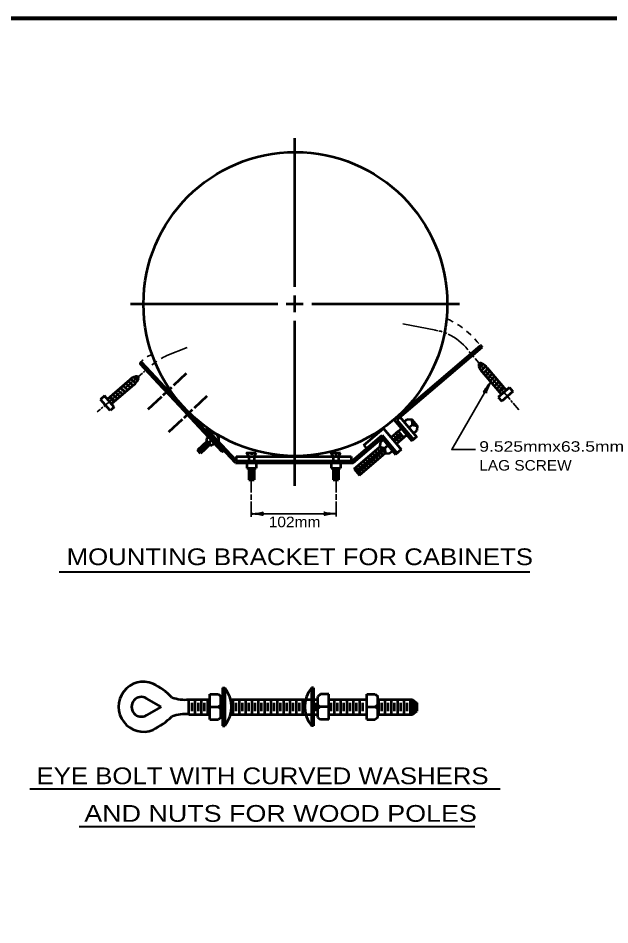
# Model space of a CAD drawing. Extents: x -34 to 821, y -14 to 530.
# Drawn here: x 424.1 to 593.8, y 264 to 523.9 of the extents above; entities that cross this region are included whole.
import ezdxf

# ---------------------------------------------------------------- set-up
doc = ezdxf.new("R2010")
doc.units = 0
doc.header["$LTSCALE"] = 1.2
doc.header["$PDMODE"] = 32
doc.header["$PDSIZE"] = 0.6
doc.linetypes.add('SHORT_DASHED', pattern=[2.7, 1.5, -1.2])
doc.layers.add('1', color=7, linetype='Continuous', lineweight=53)

msp = doc.modelspace()

# ---------------------------------------------------------------- linework, layer by layer
at = {"layer": '1'}
for p, q in [((503.473, 446.842), (503.473, 489.514)), ((503.473, 441.97), (503.473, 444.418)), ((456.313, 441.97), (498.601, 441.97)), ((500.977, 441.97), (505.801, 441.97)), ((503.473, 439.594), (503.473, 441.97)), ((508.297, 441.97), (550.657, 441.97)), ((531.865, 408.826), (556.705, 430.042)), ((532.729, 408.754), (557.113, 429.586)), ((553.033, 426.898), (553.417, 426.442)), ((554.881, 428.458), (555.265, 428.002)), ((465.721, 417.73), (459.073, 424.858)), ((486.409, 396.442), (459.505, 425.29)), ((556.249, 424.066), (557.161, 424.858)), ((556.393, 423.682), (557.305, 424.762)), ((556.897, 422.818), (558.097, 424.186)), ((558.577, 423.658), (564.073, 417.226)), ((457.297, 420.994), (458.377, 420.058)), ((457.681, 421.138), (458.473, 420.226)), ((468.721, 418.666), (472.393, 422.098)), ((557.185, 422.482), (562.681, 416.05)), ((557.545, 422.074), (558.745, 423.466)), ((558.193, 421.33), (559.393, 422.722)), ((558.817, 420.586), (560.017, 421.978)), ((559.441, 419.842), (560.665, 421.234)), ((456.121, 420.178), (449.689, 414.682)), ((457.273, 418.786), (450.865, 413.314)), ((454.201, 418.546), (455.593, 417.346)), ((454.945, 419.194), (456.337, 417.994)), ((455.689, 419.818), (457.081, 418.618)), ((456.433, 420.466), (457.801, 419.266)), ((560.089, 419.098), (561.289, 420.49)), ((560.713, 418.354), (561.937, 419.746)), ((561.361, 417.61), (562.561, 419.002)), ((451.225, 416.002), (452.617, 414.802)), ((451.969, 416.65), (453.361, 415.45)), ((452.713, 417.274), (454.105, 416.074)), ((453.457, 417.922), (454.849, 416.722)), ((465.721, 415.858), (468.217, 418.162)), ((466.153, 418.138), (465.721, 417.73)), ((467.569, 415.738), (465.721, 417.73)), ((468.001, 416.146), (467.569, 415.738)), ((564.985, 418.018), (561.769, 415.282)), ((561.985, 416.866), (563.209, 418.258)), ((563.473, 417.922), (562.105, 416.746)), ((565.969, 416.866), (562.753, 414.13)), ((564.985, 418.018), (565.969, 416.866)), ((448.897, 415.594), (447.745, 414.634)), ((450.481, 411.394), (447.745, 414.634)), ((451.633, 412.378), (448.897, 415.594)), ((451.537, 413.89), (450.361, 415.282)), ((450.481, 415.378), (451.873, 414.178)), ((461.353, 411.778), (465.289, 415.45)), ((471.697, 411.298), (467.569, 415.738)), ((474.673, 412.162), (478.345, 415.594)), ((561.769, 415.282), (562.753, 414.13)), ((451.633, 412.378), (450.481, 411.394)), ((471.673, 409.378), (474.145, 411.682)), ((472.129, 411.73), (471.697, 411.298)), ((467.281, 405.298), (471.217, 408.97)), ((474.001, 409.738), (473.569, 409.306)), ((531.865, 408.826), (536.977, 402.754)), ((532.729, 408.754), (537.433, 403.138)), ((534.769, 408.178), (535.681, 408.97)), ((536.977, 408.874), (538.537, 407.026)), ((479.017, 405.25), (478.345, 405.97)), ((486.625, 397.09), (478.369, 405.922)), ((523.249, 401.506), (528.865, 406.306)), ((533.065, 405.538), (533.977, 406.306)), ((533.065, 405.538), (534.625, 403.666)), ((536.161, 406.546), (537.073, 407.362)), ((537.529, 404.962), (538.441, 405.73)), ((478.705, 403.81), (478.033, 403.21)), ((479.521, 402.922), (478.849, 402.322)), ((519.889, 397.042), (528.505, 404.41)), ((528.817, 403.09), (527.881, 402.298)), ((528.505, 404.41), (532.801, 399.25)), ((531.697, 404.362), (533.233, 402.49)), ((531.745, 403.594), (532.513, 402.682)), ((532.369, 404.938), (533.929, 403.09)), ((532.417, 404.194), (533.209, 403.258)), ((532.561, 401.914), (535.537, 404.458)), ((533.113, 404.77), (533.905, 403.858)), ((476.713, 399.85), (476.281, 400.306)), ((477.361, 400.042), (476.521, 400.93)), ((477.577, 400.642), (477.145, 401.074)), ((478.177, 400.834), (477.361, 401.698)), ((478.393, 401.434), (478.009, 401.866)), ((478.225, 402.538), (479.065, 401.65)), ((480.337, 402.034), (479.665, 401.434)), ((523.249, 401.506), (524.017, 400.57)), ((527.113, 400.426), (528.673, 398.602)), ((527.785, 401.026), (529.369, 399.178)), ((527.833, 400.282), (528.625, 399.346)), ((530.161, 401.458), (529.249, 400.69)), ((533.953, 400.234), (532.345, 398.866)), ((476.425, 399.154), (475.585, 400.042)), ((486.625, 398.242), (519.577, 398.242)), ((486.625, 398.242), (486.625, 397.042)), ((490.249, 397.954), (490.249, 397.354)), ((490.993, 399.298), (490.993, 398.698)), ((491.761, 398.242), (492.361, 399.298)), ((491.761, 397.954), (491.761, 397.354)), ((514.441, 397.93), (514.441, 397.33)), ((515.209, 399.274), (515.209, 398.674)), ((515.953, 398.242), (516.577, 399.274)), ((515.953, 397.93), (515.953, 397.33)), ((519.577, 398.242), (519.577, 397.042)), ((522.001, 392.914), (529.369, 399.178)), ((524.353, 398.074), (525.913, 396.25)), ((525.025, 398.674), (526.609, 396.826)), ((525.073, 397.906), (525.865, 396.994)), ((525.721, 399.25), (527.305, 397.426)), ((525.769, 398.506), (526.561, 397.594)), ((526.417, 399.85), (527.977, 398.002)), ((526.465, 399.082), (527.257, 398.17)), ((527.161, 399.682), (527.929, 398.77)), ((531.529, 399.85), (530.617, 399.082)), ((486.409, 396.442), (520.177, 396.442)), ((486.625, 397.042), (519.889, 397.042)), ((489.649, 396.442), (489.649, 394.93)), ((492.361, 396.442), (492.361, 394.93)), ((513.841, 396.418), (513.841, 394.906)), ((516.577, 396.418), (516.577, 394.906)), ((520.897, 395.146), (522.457, 393.298)), ((520.897, 395.146), (522.457, 393.298)), ((521.593, 395.722), (523.153, 393.874)), ((521.641, 394.978), (522.409, 394.042)), ((522.265, 396.322), (523.849, 394.474)), ((522.313, 395.554), (523.105, 394.642)), ((522.961, 396.898), (524.545, 395.074)), ((523.009, 396.154), (523.801, 395.218)), ((523.657, 397.498), (525.217, 395.65)), ((523.705, 396.73), (524.497, 395.818)), ((524.401, 397.33), (525.169, 396.418)), ((489.649, 394.93), (492.361, 394.93)), ((490.249, 394.93), (490.249, 391.594)), ((490.249, 394.018), (491.761, 394.018)), ((490.249, 393.106), (491.761, 393.106)), ((490.537, 394.498), (491.449, 394.498)), ((490.537, 393.61), (491.449, 393.61)), ((490.537, 392.626), (491.449, 392.626)), ((491.761, 394.93), (491.761, 391.594)), ((513.841, 394.906), (516.577, 394.906)), ((514.441, 394.906), (514.441, 391.594)), ((514.441, 394.018), (515.953, 394.018)), ((514.441, 393.082), (515.953, 393.082)), ((514.753, 394.498), (515.665, 394.498)), ((514.753, 393.586), (515.665, 393.586)), ((514.753, 392.626), (515.665, 392.626)), ((515.953, 394.906), (515.953, 391.594)), ((520.441, 394.738), (522.001, 392.914)), ((490.249, 392.194), (491.761, 392.194)), ((490.249, 391.594), (491.761, 391.594)), ((514.441, 392.194), (515.953, 392.194)), ((514.441, 391.594), (515.953, 391.594)), ((479.102, 330.127), (481.526, 330.127)), ((482.726, 331.927), (482.726, 321.055)), ((482.726, 331.927), (483.35, 331.927)), ((483.35, 331.927), (483.35, 321.055)), ((508.214, 331.927), (508.214, 321.055)), ((508.814, 331.927), (508.214, 331.927)), ((508.814, 331.927), (508.814, 321.055)), ((510.758, 330.151), (510.038, 329.527)), ((513.182, 330.151), (510.758, 330.151)), ((524.053, 330.151), (526.478, 330.151)), ((526.478, 330.151), (527.197, 329.527)), ((465.11, 326.527), (460.91, 328.951)), ((473.054, 324.367), (473.054, 328.615)), ((473.054, 328.615), (479.078, 328.615)), ((473.966, 325.279), (473.966, 327.703)), ((474.877, 324.367), (474.877, 328.615)), ((475.79, 325.279), (475.79, 327.703)), ((476.678, 324.367), (476.678, 328.615)), ((477.59, 325.279), (477.59, 327.703)), ((478.502, 324.367), (478.502, 328.615)), ((482.246, 327.103), (482.246, 329.527)), ((482.246, 328.615), (482.702, 328.615)), ((485.006, 328.615), (509.966, 328.615)), ((485.75, 324.367), (485.75, 328.615)), ((486.662, 325.279), (486.662, 327.703)), ((487.574, 324.367), (487.574, 328.615)), ((488.486, 325.279), (488.486, 327.703)), ((489.398, 324.367), (489.398, 328.615)), ((490.286, 325.279), (490.286, 327.703)), ((491.198, 324.367), (491.198, 328.615)), ((492.11, 325.279), (492.11, 327.703)), ((493.022, 324.367), (493.022, 328.615)), ((493.934, 325.279), (493.934, 327.703)), ((494.822, 324.367), (494.822, 328.615)), ((495.734, 325.279), (495.734, 327.703)), ((496.646, 324.367), (496.646, 328.615)), ((497.558, 325.279), (497.558, 327.703)), ((498.47, 324.367), (498.47, 328.615)), ((499.358, 325.279), (499.358, 327.703)), ((500.27, 324.367), (500.27, 328.615)), ((501.182, 325.279), (501.182, 327.703)), ((502.094, 324.367), (502.094, 328.615)), ((503.006, 325.279), (503.006, 327.703)), ((503.894, 324.367), (503.894, 328.615)), ((504.806, 325.279), (504.806, 327.703)), ((505.718, 324.367), (505.718, 328.615)), ((509.365, 325.279), (509.365, 327.703)), ((510.038, 327.127), (510.038, 329.527)), ((513.086, 328.615), (524.005, 328.615)), ((513.878, 325.279), (513.878, 327.703)), ((514.789, 324.367), (514.789, 328.615)), ((515.702, 325.279), (515.702, 327.703)), ((516.614, 324.367), (516.614, 328.615)), ((517.502, 325.279), (517.502, 327.703)), ((518.413, 324.367), (518.413, 328.615)), ((519.326, 325.279), (519.326, 327.703)), ((520.238, 324.367), (520.238, 328.615)), ((521.149, 325.279), (521.149, 327.703)), ((522.038, 324.367), (522.038, 328.615)), ((522.95, 325.279), (522.95, 327.703)), ((527.149, 328.615), (537.158, 328.615)), ((527.197, 327.127), (527.197, 329.527)), ((527.486, 324.367), (527.486, 328.615)), ((528.398, 325.279), (528.398, 327.703)), ((529.31, 324.367), (529.31, 328.615)), ((530.221, 325.279), (530.221, 327.703)), ((531.11, 324.367), (531.11, 328.615)), ((532.022, 325.279), (532.022, 327.703)), ((532.933, 324.367), (532.933, 328.615)), ((533.846, 325.279), (533.846, 327.703)), ((534.758, 324.367), (534.758, 328.615)), ((535.645, 325.279), (535.645, 327.703)), ((536.558, 324.367), (536.558, 328.615)), ((537.158, 328.615), (537.158, 324.367)), ((537.158, 328.615), (538.382, 327.703)), ((537.782, 328.159), (537.782, 324.823)), ((538.382, 327.703), (538.382, 325.279)), ((465.11, 326.527), (460.91, 324.103)), ((479.102, 326.503), (481.526, 326.503)), ((482.246, 327.103), (482.246, 325.879)), ((482.246, 323.479), (482.246, 325.879)), ((510.038, 327.127), (510.038, 325.903)), ((510.038, 323.479), (510.038, 325.903)), ((513.182, 326.503), (510.758, 326.503)), ((524.053, 326.503), (526.478, 326.503)), ((527.197, 327.127), (527.197, 325.903)), ((527.197, 323.479), (527.197, 325.903)), ((537.158, 324.367), (538.382, 325.279)), ((473.054, 324.367), (479.078, 324.367)), ((479.102, 322.855), (481.526, 322.855)), ((482.246, 323.479), (481.526, 322.855)), ((482.246, 324.367), (482.726, 324.367)), ((485.006, 324.367), (510.038, 324.367)), ((510.038, 323.479), (510.758, 322.879)), ((513.182, 322.879), (510.758, 322.879)), ((524.053, 322.879), (526.478, 322.879)), ((527.197, 323.479), (526.478, 322.879)), ((527.197, 324.367), (537.158, 324.367)), ((482.726, 321.055), (483.35, 321.055)), ((508.814, 321.055), (508.214, 321.055))]:
    msp.add_line(p, q, dxfattribs=at)
at = {"layer": '1', "lineweight": 13}
for p, q in [((505.801, 441.97), (505.825, 441.97)), ((472.633, 410.314), (473.065, 410.698))]:
    msp.add_line(p, q, dxfattribs=at)
at = {"layer": '1', "lineweight": 35}
for p, q in [((534.409, 436.282), (543.841, 434.458)), ((543.553, 434.506), (544.513, 434.314)), ((472.609, 429.514), (466.705, 427.186)), ((553.561, 428.146), (554.737, 426.754)), ((555.121, 426.298), (557.641, 423.37)), ((557.305, 423.874), (557.785, 423.322)), ((454.633, 417.73), (459.793, 422.122)), ((558.337, 422.53), (565.153, 414.562)), ((448.657, 412.618), (453.577, 416.818)), ((453.769, 416.986), (454.321, 417.466)), ((565.393, 414.298), (565.873, 413.722)), ((566.065, 413.506), (567.697, 411.586)), ((446.761, 411.01), (447.697, 411.802)), ((447.937, 412.018), (448.417, 412.402)), ((490.945, 391.594), (490.945, 387.898)), ((515.305, 391.642), (515.305, 387.946)), ((490.945, 387.394), (490.945, 385.81)), ((515.305, 387.442), (515.305, 385.858)), ((490.945, 385.354), (490.945, 381.01)), ((515.305, 385.402), (515.305, 381.058)), ((490.945, 381.85), (515.233, 381.85))]:
    msp.add_line(p, q, dxfattribs=at)
at = {"layer": '1', "lineweight": 40}
for p, q in [((435.923, 365.194), (570.861, 365.194)), ((427.476, 303.055), (562.339, 303.055)), ((441.566, 292.231), (555.092, 292.231))]:
    msp.add_line(p, q, dxfattribs=at)
at = {"layer": '1', "lineweight": 158}
msp.add_lwpolyline([(814.88, 523.876), (23.18, 523.776), (23.28, -2.224)], dxfattribs=at)
at = {"layer": '1'}
for points in [[(503.473, 389.89), (503.473, 398.53), (503.473, 437.17)], [(482.593, 399.634), (473.569, 409.306), (471.697, 411.298)], [(533.641, 409.546), (538.369, 403.93), (536.977, 402.754)], [(535.681, 408.97), (536.977, 408.874), (537.073, 407.362), (538.537, 407.026), (538.441, 405.73)], [(528.865, 406.306), (531.001, 403.762), (532.561, 401.914), (533.953, 400.234)], [(531.001, 403.762), (532.369, 404.938), (533.065, 405.538)], [(478.033, 403.21), (478.225, 402.538), (478.849, 402.322), (479.065, 401.65), (479.665, 401.434)], [(520.177, 396.442), (528.457, 403.498), (532.345, 398.866)], [(478.225, 402.538), (476.905, 401.29), (475.585, 400.042)], [(479.065, 401.65), (477.745, 400.402), (476.425, 399.154)], [(520.441, 394.738), (527.113, 400.426), (527.785, 401.026)], [(527.881, 402.298), (527.785, 401.026), (529.249, 400.69), (529.369, 399.178), (530.617, 399.082)], [(490.249, 398.242), (489.649, 399.298), (492.361, 399.298)], [(514.441, 398.242), (513.841, 399.274), (516.577, 399.274)], [(479.102, 322.855), (479.102, 326.503), (479.102, 330.127)], [(481.526, 330.127), (482.246, 329.527), (482.246, 327.103), (481.526, 326.503), (482.246, 325.879)], [(513.182, 322.879), (513.182, 326.503), (513.182, 330.151)], [(524.053, 322.879), (524.053, 326.503), (524.053, 330.151)], [(510.038, 327.127), (510.758, 326.503), (510.038, 325.903)], [(527.197, 327.127), (526.478, 326.503), (527.197, 325.903)], [(513.134, 324.367), (524.005, 324.367), (524.053, 324.367)]]:
    msp.add_lwpolyline(points, dxfattribs=at)
at = {"layer": '1', "lineweight": 35}
msp.add_lwpolyline([(555.241, 400.258), (548.425, 400.258), (559.609, 419.65)], dxfattribs=at)
at = {"layer": '1'}
msp.add_circle((503.597, 441.944), 43.546, dxfattribs=at)
at = {"layer": '1', "linetype": 'SHORT_DASHED', "lineweight": 35}
for centre, radius, start, end in [((536.009, 414.199), 26.028, 39.09076, 64.25674), ((464.881, 420.576), 7.305, 107.18277, 136.93055), ((479.541, 402.417), 27.903, 117.40174, 135.04708)]:
    msp.add_arc(centre, radius, start, end, dxfattribs=at)
at = {"layer": '1', "lineweight": 35}
for start, end in [(72.09704, 75.39826), (66.7088, 70.55356), (37.97532, 65.20978), (34.61481, 35.37094)]:
    msp.add_arc((540.997, 419.473), 15.262, start, end, dxfattribs=at)
at = {"layer": '1'}
for centre, radius, start, end in [((556.739, 429.866), 0.176, 341.35274, 99.6479), ((557.073, 429.753), 0.176, 161.35274, 279.6479), ((556.935, 429.636), 0.176, 341.35274, 99.6479), ((459.243, 424.896), 0.176, 75.35274, 193.6479), ((459.459, 425.108), 0.176, 75.35274, 193.6479), ((459.332, 425.237), 0.176, 255.35274, 13.6479), ((557.389, 424.394), 1.193, 154.26025, 195.83671), ((559.9, 425.197), 3.829, 197.13743, 224.94055), ((556.654, 423.767), 1.193, 64.26025, 105.83671), ((555.141, 420.995), 4.35, 37.7559, 62.16939), ((458.818, 417.471), 3.829, 107.13743, 134.94055), ((458.016, 419.982), 1.193, 64.26025, 105.83671), ((457.389, 420.718), 1.193, 334.26025, 15.83671), ((454.617, 422.231), 4.35, 307.7559, 332.16939), ((478.064, 405.595), 0.176, 73.35274, 191.6479), ((478.287, 405.799), 0.176, 73.35274, 191.6479), ((478.165, 405.932), 0.176, 253.35274, 11.6479), ((478.165, 405.932), 0.176, 11.56977, 11.63706), ((479.531, 402.953), 2.166, 346.12036, 99.8792), ((482.743, 399.715), 0.176, 86.35274, 204.6479), ((482.594, 399.818), 0.176, 266.35274, 24.6479), ((482.765, 400.067), 0.176, 266.35274, 24.6479), ((460.044, 326.54), 7.152, 67.37581, 292.62419), ((454.807, 316.398), 18.552, 43.69833, 64.49446), ((476.653, 326.493), 8.622, 320.85375, 39.14625), ((514.889, 326.493), 8.622, 140.85375, 219.14625), ((459.463, 326.533), 2.823, 58.9871, 301.0129), ((472.077, 340.413), 11.844, 250.99574, 274.75423), ((452.8, 339.776), 22.213, 296.74116, 313.96028), ((472.077, 312.588), 11.844, 85.24577, 109.00426)]:
    msp.add_arc(centre, radius, start, end, dxfattribs=at)
at = {"layer": '1', "lineweight": 40}
for centre, major_axis, ratio, start_param, end_param in [((558.715, 418.608), (-1.246, -1.734), 0.07063, 6.2823074, 8.5597026), ((559.244, 418.344), (0.916, 1.965), 0.122415, 0.8963533, 3.1415927), ((492.257, 382.179), (-2.16, -0.189), 0.122415, 0.8963533, 3.1415927), ((513.879, 382.1), (-2.125, 0.212), 0.07063, 6.2823074, 8.5597026), ((492.293, 381.589), (2.125, -0.212), 0.07063, 6.2823074, 8.5597026), ((513.915, 381.51), (2.16, 0.189), 0.122415, 0.8963533, 3.1415927)]:
    msp.add_ellipse(centre, major_axis=major_axis, ratio=ratio, start_param=start_param, end_param=end_param, dxfattribs=at)
at = {"layer": '1'}
msp.add_point((478.345, 405.97), dxfattribs=at)

# ---------------------------------------------------------------- texts
for s, height, width, p in [('9.525mmx63.5mm', 3, 1.25, (556.323, 399.627)), ('LAG SCREW', 3, 1.1, (556.323, 394.227)), ('102mm', 3.024, 1.1, (495.953, 377.995)), ('MOUNTING BRACKET FOR CABINETS', 4.8, 1.15, (438.029, 367.123)), ('EYE BOLT WITH CURVED WASHERS', 4.8, 1.15, (429.388, 304.346)), ('AND NUTS FOR WOOD POLES', 4.8, 1.2, (443.076, 293.573))]:
    msp.add_text(s, height=height, dxfattribs=dict(at, width=width)).set_placement(p)

doc.saveas('drawing.dxf')
